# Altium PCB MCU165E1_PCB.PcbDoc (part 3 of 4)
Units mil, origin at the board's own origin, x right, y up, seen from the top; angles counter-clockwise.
Board outline 2658.83 x 2179.35 mil, 6 copper layers (Top Signal Layer, GND1, Mid Layer, PWR, GND2, Bottom Signal Layer), stack 60.4 mil thick; 226 components, 197 nets, 947 pads, 562 vias.
Unrouted connection lines stored in the file: 81.
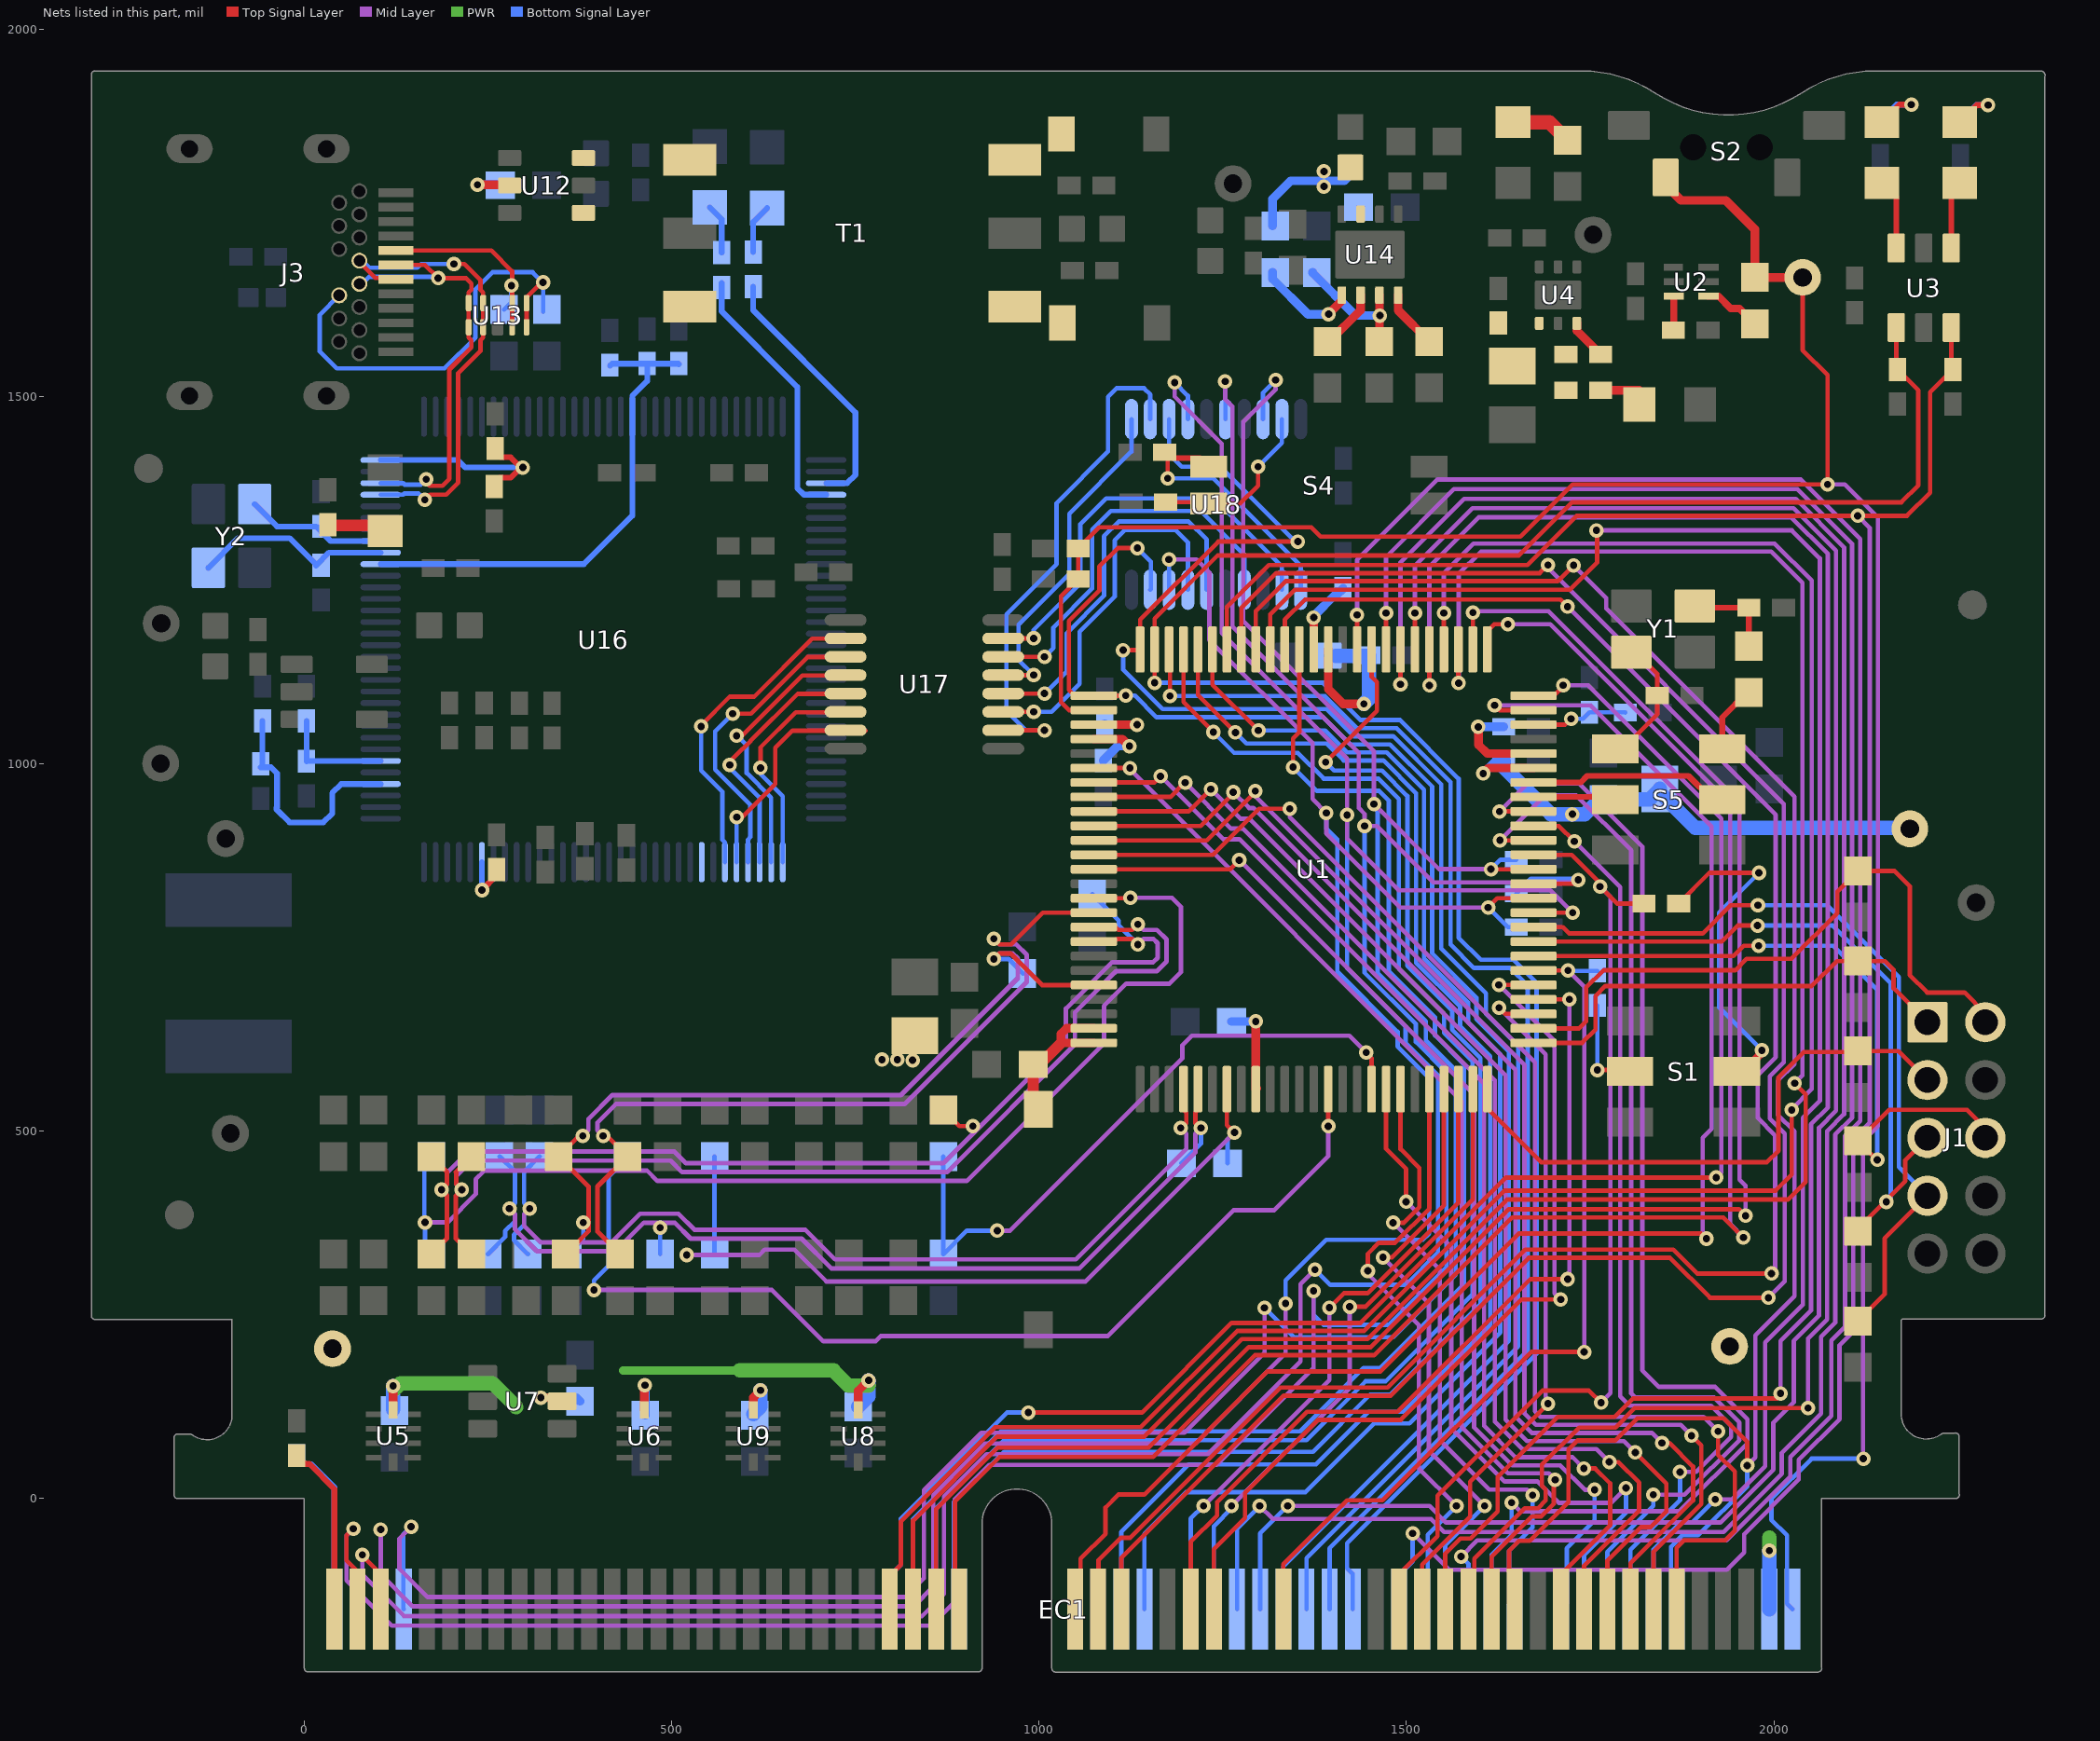
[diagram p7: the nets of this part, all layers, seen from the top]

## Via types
v1: diameter 19.68, hole 9.84, Top Signal Layer to Bottom Signal Layer, tented both sides, 540 vias
v2: diameter 23.62, hole 11.81, Top Signal Layer to Bottom Signal Layer, tented both sides, 16 vias
v3: diameter 19.68, hole 7.99, Top Signal Layer to Bottom Signal Layer, tented bottom, 4 vias
v4: diameter 19.68, hole 7.87, Top Signal Layer to Bottom Signal Layer, tented bottom, 2 vias

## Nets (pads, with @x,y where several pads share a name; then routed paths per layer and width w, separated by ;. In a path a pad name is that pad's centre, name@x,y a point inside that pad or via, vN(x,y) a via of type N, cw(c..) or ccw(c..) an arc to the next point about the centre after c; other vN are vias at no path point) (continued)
MCU_B2/C6/E12: C45.1 R42.1 U1.15 | length 1571.2
  Top Signal Layer w6: U1.15@1074.57,816.94 1123.72,816.94 v1(1124.28,817.5)
  Mid Layer w6: v1(164.39,375.65) 195.05,375.65 233.47,414.07 233.47,434.36 245.31,446.2 466.7,446.2 480.72,432.18 901.66,432.18 1088.46,618.98 1088.46,670.39 1118.73,700.66 1177.52,700.66 1193,716.14 1193,805.56 1181.06,817.5 v1(1124.28,817.5)
  Bottom Signal Layer w6: C45.1@157.33,460.85 163.33,454.86 163.33,376.71 v1(164.39,375.65) 164.39,341.21 R42.1@173.1,332.5
MCU_B4/C8: C47.1 R40.1 U1.39 | length 1433.5
  Top Signal Layer w6: U1.39@1393.47,557.1 1393.47,506.6 v1(1393.59,506.48)
  Mid Layer w6: v1(394.17,283.73) 636.45,283.73 706.21,213.97 777.55,213.97 784.71,221.13 1093.59,221.13 1264.68,392.22 1319.92,392.22 1393.59,465.89 v1(1393.59,506.48)
  Bottom Signal Layer w6: v1(394.17,283.73) 394.17,296.79 R40.1@429.89,332.5 414.17,348.22 414.17,437.83 429.95,453.61 C47.1@429.95,465.5
MCU_B5/D15/E15/PGA3_OUT: C43.1 C98.2 R44.1 U1.32 | length 1132.9
  Top Signal Layer w6: U1.32@1255.68,557.1 1255.68,508.32 v1(1265.91,498.09)
  Mid Layer w6: v1(520.47,331.39) 619.21,331.39 626.38,338.56 667.23,338.56 710.46,295.33 1063.15,295.33 v1(1265.91,498.09)
  Bottom Signal Layer w6: v1(520.47,331.39) 559.46,331.39 R44.1@558.35,332.5 C43.1@558.35,465.44 ; C98.2@1256.49,456.13 1256.49,488.67 v1(1265.91,498.09)
MCU_C14: C52.1 R49.1 U1.42 | length 904.2
  Top Signal Layer w6: v1(1445.09,606.85) 1452.53,599.41 U1.42@1452.53,557.1
  Mid Layer w6: v1(943.13,364.5) 960.66,364.5 1194.96,598.8 1194.96,616.76 1207.86,629.66 1422.28,629.66 v1(1445.09,606.85)
  Bottom Signal Layer w6: C52.1@869.74,465.44 R49.1@869.74,332.5 901.74,364.5 v1(943.13,364.5)
MCU_GPIO0: EC1.49 U1.79 | length 2999.7
  Top Signal Layer w6: EC1.49@796.97,-150.67 796.97,-104.87 811.95,-89.89 811.95,-31.19 940.07,96.93 1138.44,96.93 1269.43,227.92 1442.28,227.92 1633.3,418.94 2002.41,418.94 2024.18,440.71 v1(2024.18,528.79) ; U1.79@1550.95,1155.53 v1@1550.95,1204.96
  Mid Layer w6: v1(1550.93,1204.98) 1550.93,1259.6 1591.02,1299.69 2001.03,1299.69 2051.56,1249.16 2051.56,557.22 2024.18,529.84 v1(2024.18,528.79)
  PWR w6: v1(2024.18,528.79) 2024.18,530.06 v1@2026.3,532.18
MCU_GPIO1: EC1.51 U1.78 | length 3044.7
  Top Signal Layer w6: EC1.51@828.46,-150.67 828.46,-30.23 942.88,84.18 1143.1,84.18 1275.84,216.92 1446.84,216.92 1636.72,406.8 2019.08,406.8 2043.21,430.93 2043.21,550.15 v1(2028.37,564.99) ; U1.78@1570.64,1155.53 1570.64,1110.09 v1(1571.09,1109.64)
  Mid Layer w6: v1(1571.09,1109.64) 1571.09,1258.09 1601.69,1288.69 1996.48,1288.69 2039,1246.16 2039,575.62 v1(2028.37,564.99)
MCU_GPIO2: EC1.53 U1.77 | length 2498.3
  Top Signal Layer w6: EC1.53@859.96,-150.67 859.96,-14.29 943.47,69.22 1148.9,69.22 1285.6,205.92 1451.39,205.92 1639.03,393.56 1952.55,393.56 v1(1961.39,384.72) ; U1.77@1590.32,1155.53 1590.32,1205.57 v1(1590.44,1205.69)
  Mid Layer w6: v1(1590.44,1205.69) 1592.34,1207.59 1693.5,1207.59 1953.32,947.78 1953.32,433.84 1961.39,425.77 v1(1961.39,384.72)
MCU_GPIO3: EC1.55 U1.76 | length 2442.8
  Top Signal Layer w6: EC1.55@885.42,-144.63 885.42,-4.39 946.4,56.59 1155.51,56.59 1293.84,194.92 1455.95,194.92 1643.59,382.56 1931.3,382.56 v1(1958.56,355.3) ; U1.76@1610.01,1155.53 1610.01,1180.41 1619.35,1189.75 v1(1637.92,1189.75)
  Mid Layer w6: v1(1637.92,1189.75) 1695.79,1189.75 1940.57,944.97 1940.57,373.29 v1(1958.56,355.3)
MCU_GPIO4: EC1.50 U1.75 | length 2260.9
  Top Signal Layer w6: v1(985.4,116.92) 1139.94,116.92 1261.94,238.92 1437.72,238.92 1635.59,436.79 v1(1921.48,436.79) ; U1.75@1673,1092.54 1700.77,1092.54 1713.28,1105.05 v1(1713.28,1106.65)
  Mid Layer w6: v1(1713.28,1106.65) 1747.37,1106.65 1928.6,925.42 1928.6,443.36 1921.99,436.75 v1(1921.48,436.79) v1(1921.48,436.79)
  PWR w6: v1@1921.48,436.58 v1(1921.48,436.79)
  Bottom Signal Layer w6: EC1.50@796.97,-150.67 796.97,-104.87 811.95,-89.89 811.95,-27.38 956.25,116.92 v1(985.4,116.92)
MCU_GPIO5: EC1.52 U1.89 | length 2018.6
  Top Signal Layer w6: v1(1345.51,995.35) 1345.51,1034.23 1354.1,1042.82 U1.89@1354.1,1155.53
  Bottom Signal Layer w6: EC1.52@828.46,-150.67 828.46,-27.92 947.74,91.36 1355.01,91.36 1441.36,177.71 1464.15,177.71 1578.27,291.83 1578.27,590.77 1538.87,630.17 1538.87,654.77 1475.92,717.72 1475.92,950.23 1463.15,963 1377.86,963 v1(1345.51,995.35)
MCU_GPIO6: EC1.54 U1.97 | length 2123
  Top Signal Layer w6: U1.97@1196.62,1155.53 1196.62,1084.06 1237.14,1043.54 v1(1237.14,1043.02)
  Bottom Signal Layer w6: EC1.54@859.96,-150.67 859.96,-13.3 952.38,79.12 1363.97,79.12 1444.37,159.52 1471.64,159.52 1589.72,277.6 1589.72,594.88 1551.11,633.49 1551.11,659.73 1489.56,721.28 1489.56,952.15 1462,979.71 1387.3,979.71 1352.27,1014.74 1265.42,1014.74 v1(1237.14,1043.02)
MCU_GPIO7: EC1.56 U1.84 | length 2015.3
  Top Signal Layer w6: v1(1390.01,1002.23) 1459.76,1071.98 1459.76,1111.09 1452.53,1118.32 U1.84@1452.53,1155.53
  Bottom Signal Layer w6: EC1.56@884.28,-143.49 884.28,-4.54 952.29,63.47 1372.94,63.47 1450.6,141.13 1477.64,141.13 1600.78,264.27 1600.78,599.37 1562.11,638.04 1562.11,664.29 1501.22,725.18 1501.22,956.05 1466.56,990.71 1401.53,990.71 v1(1390.01,1002.23)
MCU_GPIO8: EC1.57 U1.74 | length 2107.5
  Top Signal Layer w6: EC1.57@1056.53,-143.08 1056.53,-82.1 1090.44,-48.19 1090.44,-12.37 1108.09,5.29 1143.24,5.29 1310.87,172.92 1465.06,172.92 1652.7,360.56 1901.29,360.56 v1(1908.25,353.6) ; v1(1619.96,1079.41) 1626.52,1072.85 U1.74@1673,1072.85
  Mid Layer w6: v1(1619.96,1079.41) 1750.52,1079.41 1915.27,914.66 1915.27,502.95 1903.1,490.78 1903.1,358.75 v1(1908.25,353.6)
MCU_GPIO9: EC1.59 U1.90 | length 2659.5
  Top Signal Layer w6: EC1.59@1080.72,-151.11 1080.72,-84.17 1111.33,-53.57 1124.07,-53.57 1328.56,150.92 1474.18,150.92 1661.82,338.56 1863.21,338.56 1895.73,306.04 v1(1996.84,306.04) ; U1.90@1334.42,1155.53 1334.42,1196.03 1361.92,1223.53 1709.51,1223.53 v1(1719.3,1213.74)
  Mid Layer w6: v1(1719.3,1213.74) 2002.51,930.53 2002.51,600.73 1977.95,576.17 1977.95,517.94 2001.76,494.13 2001.76,310.96 v1(1996.84,306.04)
MCU_GPIO10: EC1.61 U1.93 | length 2795.2
  Top Signal Layer w6: EC1.61@1111.93,-150.67 1111.93,-81.27 1333.12,139.92 1478.73,139.92 1666.37,327.56 1858.65,327.56 1913.06,273.15 v1(1992.58,273.15) ; U1.93@1275.36,1155.53 1275.36,1212.04 1322.73,1259.41 1681.4,1259.41 1692.31,1270.32 v1(1692.45,1270.32)
  Mid Layer w6: v1(1692.45,1270.32) 1692.45,1266.29 2013.51,945.23 2013.51,593.41 1994.56,574.46 1994.56,516.88 2014.68,496.76 2014.68,295.25 v1(1992.58,273.15)
MCU_GPIO11: J1.2 R4.2 U1.52 | length 910.8
  Top Signal Layer w6: U1.52@1673,639.78 1735.12,639.78 1744.58,649.24 1744.58,695.46 1767.92,718.8 1947.46,718.8 1962.99,734.33 2023.96,734.33 2086.47,796.84 2086.47,826.05 R4.2@2114.35,853.93 2164.37,853.93 2185.03,833.27 2185.03,712.19 2208.66,688.56 2259.44,688.56 2287.74,660.26 J1.2@2287.74,648.22
MCU_GPIO12: J1.1 R3.2 U1.51 | length 658.1
  Top Signal Layer w6: U1.51@1673,620.09 1739.11,620.09 1757.19,638.17 1757.19,683.87 1770.73,697.41 2051.67,697.41 2085.71,731.45 R3.2@2114.35,731.45 2150.91,731.45 2162.95,719.41 2162.95,694.27 J1.1@2209,648.22
MCU_GPIO13: J1.3 R5.2 U1.50 | length 774.3
  Top Signal Layer w6: U1.50@1610.01,557.1 1610.01,531.05 1683.33,457.73 1990.71,457.73 2006.25,473.27 2006.25,573.15 2040.56,607.46 R5.2@2096.34,607.46 ; R5.2@2114.35,608.97 2169.51,608.97 J1.3@2209,569.48
MCU_GPIO14: EC1.62 U1.96 | length 1903.3
  Top Signal Layer w6: U1.96@1216.31,1155.53 1216.31,1093.43 v1(1267.26,1042.48)
  Bottom Signal Layer w6: EC1.62@1111.93,-150.67 1111.93,-45.59 1203.83,46.31 1376.92,46.31 1448.61,118 1495.79,118 1613.83,236.04 1613.83,601.88 1573.11,642.6 1573.11,668.84 1512.98,728.97 1512.98,959.84 1468.45,1004.37 1414.53,1004.37 1391.57,1027.33 1282.41,1027.33 v1(1267.26,1042.48)
MCU_GPIO15: EC1.64 U1.95 | length 1877
  Top Signal Layer w6: U1.95@1235.99,1155.53 1235.99,1107.64 v1(1298.46,1045.17)
  Bottom Signal Layer w6: EC1.64@1143.42,-150.67 1143.42,-48.12 1200.18,8.64 1362.72,8.64 1456.15,102.07 1504,102.07 1627.65,225.72 1627.65,604.62 1584.11,648.16 1584.11,675.08 1523.98,735.21 1523.98,964.4 1473.01,1015.37 1419.09,1015.37 1389.29,1045.17 v1(1298.46,1045.17)
MCU_GPIO16: EC1.67 U1.54 | length 1208.9
  Top Signal Layer w6: EC1.67@1206.42,-150.67 1206.42,-58.98 1242.22,-23.18 1242.22,-4.76 1364.91,117.92 1487.84,117.92 1668.34,298.42 v1(1719.43,298.42) ; U1.54@1673,679.15 v1(1721.88,679.15)
  Mid Layer w6: v1@1717.42,679.15 v1(1721.88,679.15) 1721.88,297.88 v1@1719.43,295.43 ; v1@1717.6,293.6 v1@1719.43,295.43 ; v1(1719.43,298.42) v1@1719.43,295.43
  PWR w6: v1@1718.2,297.19 v1(1719.43,298.42)
MCU_GPIO17: EC1.69 U1.55 | length 1224.4
  Top Signal Layer w6: EC1.69@1237.91,-150.67 1237.91,-69.16 1280.49,-26.58 1280.49,7.51 1379.9,106.92 1492.4,106.92 1656.34,270.86 v1(1709.98,270.86) ; v1(1625.8,698.83) U1.55@1673,698.83
  Mid Layer w6: v1(1625.8,698.83) 1701.58,623.05 1701.58,279.26 v1(1709.98,270.86)
MCU_GPIO18/X2: S5.2 U1.68 | length 112.6
  Top Signal Layer w8: U1.68@1673,954.74 1780.69,954.74 S5.2@1784.17,951.26
MCU_GPIO19/X1: S5.5 U1.69 | length 273.9
  Top Signal Layer w8: U1.69@1673,974.43 1737.06,974.43 1746.02,983.39 1883.82,983.39 1915.95,951.26 S5.5@1929.83,951.26
MCU_GPIO20: EC1.68 U1.48 | length 877.5
  Top Signal Layer w6: v1(1395.14,259.6) 1414.84,279.3 1446.99,279.3 1570.64,402.95 U1.48@1570.64,557.1
  Mid Layer w6: v1(1223.78,-10.2) 1395.14,161.16 v1(1395.14,259.6)
  Bottom Signal Layer w6: EC1.68@1206.42,-150.67 1206.42,-27.57 v1(1223.78,-10.2)
MCU_GPIO21: EC1.70 U1.49 | length 864.7
  Top Signal Layer w6: v1(1422.83,260.95) 1444.2,260.95 1590.32,407.07 U1.49@1590.32,557.1
  Mid Layer w6: v1(1262.02,-10.2) 1422.83,150.61 v1(1422.83,260.95)
  Bottom Signal Layer w6: EC1.70@1237.91,-150.67 1237.91,-37.75 v1@1263.38,-12.28
MCU_GPIO22: EC1.72 U1.83 | length 3045
  Top Signal Layer w6: v1@1299.1,-17.04 v1@1300.31,-17.04 ; U1.83@1472.21,1155.53 v1(1472.2,1205.03)
  Mid Layer w6: v1(1300.25,-10.2) 1318.09,-28.04 1533.68,-28.04 1551.2,-45.57 1931.56,-45.57 2010.78,33.66 2010.78,62.07 2064.37,115.66 2064.37,220.04 2083.51,239.17 2083.51,495.41 2106.56,518.46 2106.56,1299.16 2032.1,1373.62 1564.33,1373.62 1472.2,1281.49 v1(1472.2,1205.03)
  Bottom Signal Layer w6: EC1.72@1269.41,-150.67 1269.41,-41.27 1298.91,-11.77 v1@1299.1,-11.77
MCU_GPIO23: EC1.74 U1.81 | length 2885.6
  Top Signal Layer w6: U1.81@1511.58,1155.53 v1(1511.57,1205.11)
  Mid Layer w6: v1(1338.49,-10.2) 1531.39,-10.2 1553.88,-32.69 1927.17,-32.69 1999.32,39.46 1999.32,103.18 2027.06,130.92 2027.06,214.54 2061.51,248.99 2061.51,504.52 2084.56,527.57 2084.56,1290.05 2026.79,1347.82 1589.84,1347.82 1511.57,1269.55 v1(1511.57,1205.11)
  Bottom Signal Layer w6: EC1.74@1300.9,-150.67 1300.9,-47.47 1337.71,-10.66 v1@1338.79,-10.66
MCU_GPIO24: EC1.75 R9.2 U1.56 | length 1215.7
  Top Signal Layer w6: EC1.75@1332.4,-150.67 1332.4,-89.56 1419.26,-2.7 1467.55,-2.7 1669.67,199.42 v1(1741.85,199.42) ; U1.56@1673,718.52 v1(1719.72,718.52)
  Mid Layer w6: v1(1719.72,718.52) 1741.96,696.28 1741.96,194.35 1741.85,194.46 v1(1741.85,199.42)
  Bottom Signal Layer w6: v1(1719.72,718.52) 1720.17,718.07 R9.2@1759.8,718.07
MCU_GPIO25: J1.6 R6.2 U1.57 | length 981.7
  Top Signal Layer w6: U1.57@1673,738.2 1944.93,738.2 1958.95,752.22 v1(1979.36,752.22) ; v1(2140.82,460.85) 2139.99,460.85 R6.2@2114.35,486.49 2156.86,529 2263,529 2287.74,504.26 J1.6@2287.74,490.74
  Bottom Signal Layer w6: v1(1979.36,752.22) 2080.8,752.22 2140.82,692.2 v1(2140.82,460.85)
MCU_GPIO26: J1.5 R7.2 U1.58 | length 993.5
  Top Signal Layer w6: U1.58@1673,757.89 1673.11,758 1928.91,758 1950.69,779.78 v1(1977.82,779.78) ; R7.2@2114.35,364.02 2114.35,367.36 2178.78,431.79 2178.78,460.52 J1.5@2209,490.74
  Bottom Signal Layer w6: v1(1977.82,779.78) 2080.13,779.78 2159.18,700.73 2159.18,409.89 v1(2152.98,403.69)
MCU_GPIO27: J1.7 R8.2 U1.59 | length 1080.6
  Top Signal Layer w6: U1.59@1673,777.57 1712.99,777.57 1721.56,769 1903.05,769 1941.43,807.38 v1(1978.3,807.38) ; R8.2@2114.35,241.54 2150.74,277.93 2150.74,353.74 J1.7@2209,412
  Bottom Signal Layer w6: v1(1978.3,807.38) 2072.55,807.38 2170.18,709.75 2170.18,450.82 J1.7@2209,412
MCU_GPIO28: EC1.76 U1.1 U18.9 | length 2150.5
  Top Signal Layer w6: v1(1117.96,1092.69) 1117.81,1092.54 U1.1@1074.57,1092.54 1048.54,1092.54 1040.65,1100.43 1040.65,1193.98 1082.11,1235.44 1082.11,1268.24 1107.27,1293.4 v1(1133.82,1293.4)
  Bottom Signal Layer w6: v1(1117.96,1092.69) 1130.63,1092.69 1160.05,1063.27 1386.75,1063.27 1423.64,1026.37 1477.56,1026.37 1534.98,968.95 1534.98,742.06 1595.11,681.93 1595.11,652.72 1639.3,608.53 1639.3,214.24 1332.4,-92.66 EC1.76@1332.4,-150.67 ; v1(1133.82,1293.4) 1152.08,1275.14 1152.08,1237.51 U18.9@1151.34,1236.77
MCU_GPIO29: EC1.78 U1.100 U18.13 | length 2404.6
  Top Signal Layer w6: v1(1114.35,1154.57) 1136.61,1154.57 U1.100@1137.57,1155.53 1137.57,1196.03 1243.91,1302.37 v1(1352.21,1302.37)
  Bottom Signal Layer w6: v1(1114.35,1154.57) 1114.35,1128.05 1168.13,1074.27 1391.3,1074.27 1428.2,1037.37 1482.12,1037.37 1547.51,971.98 1547.51,748.15 1608.25,687.41 1608.25,659.87 1652.16,615.96 1652.16,207.01 1363.9,-81.25 EC1.78@1363.9,-150.67 ; U18.13@1176.93,1469.06 1176.93,1421.65 1194.38,1404.2 1246.93,1404.2 1348.76,1302.37 v1(1352.21,1302.37)
MCU_GPIO30: EC1.80 U1.98 | length 1804.1
  Top Signal Layer w6: U1.98@1176.94,1155.53 1178.21,1154.25 1178.21,1092.11 v1(1178.26,1092.11)
  Bottom Signal Layer w6: v1(1178.26,1092.11) 1389.02,1092.11 1432.76,1048.37 1486.68,1048.37 1559.92,975.13 1559.92,753.85 1591.71,722.06 1641.29,722.06 1664.99,698.36 1664.99,201.5 1395.39,-68.09 EC1.80@1395.39,-150.67
MCU_GPIO31: EC1.82 R21.1 U1.99 U3.1 | length 3204.7
  Top Signal Layer w6: v1(1157.4,1110.23) 1157.4,1155.38 U1.99@1157.25,1155.53 1157.25,1197.55 1243.22,1283.52 1653.12,1283.52 1725.39,1355.79 2173.57,1355.79 2196.58,1378.8 2196.58,1508.23 R21.1@2168.19,1536.62 ; R21.1@2166.6,1538.21 U3.1@2166.6,1593.58
  Bottom Signal Layer w6: v1(1157.4,1110.23) 1386.45,1110.23 1437.31,1059.37 1491.23,1059.37 1571.12,979.48 1571.12,763.19 1601.25,733.06 1645.85,733.06 1676.99,701.92 1676.99,196.66 1419.21,-61.12 1419.21,-94.83 1426.89,-102.51 EC1.82@1426.89,-150.67
MCU_GPIO32: EC1.85 R10.1 U1.64 | length 1358.9
  Top Signal Layer w6: EC1.85@1489.88,-150.67 1489.88,-103.5 1542.24,-51.14 1542.24,3.83 1685.23,146.82 1748.42,146.82 v1(1764.83,130.41) ; U1.64@1673,876 1724.84,876 1763.37,837.47 v1(1763.37,832.9) 1786.62,809.65 R10.1@1823.26,809.65
  Mid Layer w6: v1(1763.37,832.9) 1777.64,818.63 1777.64,143.22 v1(1764.83,130.41)
MCU_GPIO33: EC1.87 U1.53 | length 967.3
  Top Signal Layer w6: EC1.87@1521.38,-150.67 1521.38,-89.9 1586.62,-24.66 1586.62,22.98 v1(1692.62,128.98) ; v1(1626.09,667.8) 1634.43,659.46 U1.53@1673,659.46
  Mid Layer w6: v1(1626.09,667.8) 1689.54,604.35 1689.54,132.06 v1(1692.62,128.98)
MCU_GPIO34: EC1.86 R22.1 U1.94 U3.3 | length 3395.3
  Top Signal Layer w6: U1.94@1255.68,1155.53 1255.68,1213.54 1312.55,1270.41 1664.59,1270.41 1731.39,1337.21 v1@2114.07,1337.21 ; v1(2114.07,1337.32) 2181.15,1337.32 2212.53,1368.7 2212.53,1505.55 R22.1@2243.61,1536.62 ; R22.1@2241.4,1538.83 U3.3@2241.4,1593.58
  Mid Layer w6: v1(1508.47,-47.45) 1557.95,-96.93 1936.22,-96.93 1959.62,-73.53 1959.62,-48.62 2033.97,25.73 2033.97,52.39 2089.35,107.77 2089.35,208.57 2107.9,227.12 2107.9,488.69 2130.48,511.27 2130.48,1320.91 v1(2114.07,1337.32)
  Bottom Signal Layer w6: EC1.86@1489.91,-150.64 1489.91,-104.09 1508.47,-85.53 v1(1508.47,-47.45)
MCU_GPIO35/TDI: EC1.8 R11.1 U1.63 U18.18 | length 3664.7
  Top Signal Layer w6: v1(1614.98,856.43) 1615.1,856.32 U1.63@1673,856.32
  Mid Layer w6: v1(145.49,-38.49) 129.5,-54.48 129.5,-95.6 168.13,-134.23 817.99,-134.23 843.48,-108.74 843.48,11.3 921.51,89.33 1197.88,89.33 1306.81,198.26 v1(1306.81,259.36) ; v1(1321.92,1522.17) 1321.92,1509.3 1277.9,1465.28 1277.9,1194.44 1455.76,1016.58 v1(1455.76,945.16) 1544.49,856.43 v1(1614.98,856.43)
  Bottom Signal Layer w6: EC1.8@135.55,-150.67 134.93,-150.05 134.93,-49.05 v1(145.49,-38.49) ; U18.18@1304.88,1469.06 1304.88,1505.13 v1(1321.92,1522.17) ; v1(1306.81,259.36) 1346.81,219.36 1481.9,219.36 1567.01,304.47 1567.01,582.73 1526.26,623.48 1526.26,649.4 1460.85,714.81 1460.85,940.07 v1(1455.76,945.16) ; v1(1614.98,856.43) 1627.92,869.37 R11.1@1649.38,869.37
MCU_GPIO37/TDO: EC1.6 R12.1 U1.61 U18.8 | length 3488.7
  Top Signal Layer w6: v1(1611.11,804.37) 1623.68,816.94 U1.61@1673,816.94
  Mid Layer w6: v1(103.99,-42.19) 103.99,-102.98 147.88,-146.87 829.36,-146.87 856.08,-120.15 856.08,4.38 926.63,74.93 1212.79,74.93 1335.53,197.67 v1(1335.53,265.38) ; v1(1176.71,1277.87) 1214.17,1277.87 1231.68,1260.36 1231.68,1168.51 1372.17,1028.02 1372.17,951.87 v1@1390.95,933.09 ; v1(1390.89,933.03) 1390.89,905.27 1491.79,804.37 v1(1611.11,804.37)
  Bottom Signal Layer w6: v1(103.99,-42.19) 103.99,-150.61 EC1.6@104.05,-150.67 ; v1(1176.71,1277.87) 1176.93,1277.65 U18.8@1176.93,1236.77 ; v1(1335.53,265.38) 1335.53,296.75 1390.66,351.88 1522.21,351.88 1530.7,360.37 1530.7,572.37 1487.96,615.11 1487.96,635.18 1405.74,717.39 1405.74,897.1 1390.89,911.95 v1(1390.89,933.03) ; v1(1611.11,804.37) 1637.91,777.57 R12.1@1649.38,777.57
MCU_GPIO40: EC1.89 U1.80 | length 2622.8
  Top Signal Layer w6: v1(1531.25,1106.56) U1.80@1531.27,1155.53 ; EC1.89@1552.87,-150.67 1552.87,-74.81 1573.3,-54.39 1587.36,-54.39 1624.16,-17.59 1624.16,29.01 1706.01,110.86 1783.11,110.86 1808.17,135.92 2004.8,135.92 v1@2011.63,142.75
  Mid Layer w6: v1(1531.25,1106.56) 1531.25,1268.41 1598.21,1335.37 2023.68,1335.37 2073.56,1285.49 2073.56,532.13 2050.51,509.08 2050.51,255.57 2009.22,214.28 v1(2009.22,142.94)
MCU_GPIO41: EC1.91 U1.82 | length 2719.3
  Top Signal Layer w6: v1(1491.84,1107.91) 1491.9,1107.97 U1.82@1491.9,1155.53 ; EC1.91@1584.37,-150.67 1592.22,-142.82 1592.22,-81.85 1660.78,-13.29 1679.02,-13.29 1689.47,-2.84 1689.47,11.94 1684.44,16.98 1684.44,46.04 1734.94,96.55 1784.36,96.55 1810.86,123.05 v1(2046.53,123.05)
  Mid Layer w6: v1(1491.84,1107.91) 1491.84,1273.8 1578.45,1360.41 2029.75,1360.41 2095.56,1294.6 2095.56,523.02 2072.51,499.97 2072.51,243.73 2046.53,217.75 v1(2046.53,123.05)
MCU_GPIO44: EC1.92 U1.85 | length 2770.1
  Top Signal Layer w6: v1(1432.73,1202.65) 1432.84,1202.54 U1.85@1432.84,1155.53
  Mid Layer w6: v1(1432.73,1202.65) 1432.73,1277.44 1542.18,1386.89 2036.6,1386.89 2117.56,1305.93 2117.56,513.9 2096.9,493.24 2096.9,233.49 2078.35,214.94 2078.35,112.33 2022.25,56.23 2022.25,29.57 1935.6,-57.08 1596.39,-57.08 v1(1574.38,-79.09)
  Bottom Signal Layer w6: v1(1574.38,-79.09) 1584.37,-89.08 EC1.92@1584.37,-150.67
MCU_GPIO47: EC1.93 U1.6 | length 1509.1
  Top Signal Layer w6: U1.6@1074.57,994.11 v1(1123.64,994.08) ; EC1.93@1615.87,-150.67 1615.87,-79.46 1671.03,-24.29 1683.58,-24.29 1700.47,-7.4 1700.47,23.69 v1(1702.28,25.5)
  Mid Layer w6: v1(1123.64,994.08) 1123.64,992.29 1575.24,540.69 1575.24,97.19 1638.29,34.14 1693.64,34.14 v1(1702.28,25.5)
MCU_GPIO48: EC1.99 U1.7 | length 1576.3
  Top Signal Layer w6: U1.7@1074.57,974.43 1156.9,974.43 v1(1165.26,982.79) ; EC1.99@1710.35,-150.67 1710.35,-103.43 1777.23,-36.55 1777.23,20.62 1756.95,40.9 v1(1741.27,40.9)
  Mid Layer w6: v1(1165.26,982.79) 1250.81,897.24 1272.58,897.24 1605.61,564.21 1605.61,98.7 1648.17,56.14 1726.03,56.14 v1(1741.27,40.9)
MCU_GPIO49: EC1.101 U1.8 | length 1620.2
  Top Signal Layer w6: U1.8@1074.57,954.74 1178.59,954.74 1198.18,974.33 v1(1198.97,974.33) ; EC1.101@1741.85,-150.67 1741.85,-91.3 1816.6,-16.55 1816.6,21.58 1788.55,49.63 v1(1776.06,49.63)
  Mid Layer w6: v1(1198.97,974.33) 1261.59,911.71 1277.76,911.71 1620.31,569.16 1620.31,104.46 1657.63,67.14 1758.55,67.14 v1(1776.06,49.63)
MCU_GPIO50: EC1.103 U1.9 | length 1669.8
  Top Signal Layer w6: U1.9@1074.57,935.06 1203.44,935.06 v1(1233.79,965.41) ; EC1.103@1773.35,-150.67 1773.35,-84.77 1819.09,-39.03 1832.35,-39.03 1853.79,-17.59 1853.79,20.22 v1(1811.37,62.64)
  Mid Layer w6: v1(1233.79,965.41) 1274.03,925.17 1285.85,925.17 1635.01,576.01 1635.01,107.44 1664.31,78.14 1795.87,78.14 v1(1811.37,62.64)
MCU_GPIO51: EC1.105 U1.10 | length 1721.3
  Top Signal Layer w6: U1.10@1074.57,915.37 1220.05,915.37 1264.21,959.53 v1(1264.21,961.19) ; EC1.105@1804.84,-150.67 1804.84,-88.15 1890.14,-2.85 1890.14,43.38 1857.96,75.56 v1(1847.69,75.56)
  Mid Layer w6: v1(1264.21,961.19) 1285.75,939.65 1291.74,939.65 1648.05,583.34 1648.05,111.74 1670.65,89.14 1834.11,89.14 v1(1847.69,75.56)
MCU_GPIO52: EC1.107 U1.11 | length 1755.1
  Top Signal Layer w6: U1.11@1074.57,895.69 1228.34,895.69 1294.31,961.66 v1(1294.31,962.66) ; EC1.107@1836.34,-150.67 1836.34,-72.21 1901.14,-7.41 1901.14,72.27 v1(1888.05,85.36)
  Mid Layer w6: v1(1294.31,962.66) 1294.31,956.05 1660.67,589.69 1660.67,115.64 1676.17,100.14 1873.27,100.14 v1(1888.05,85.36)
MCU_GPIO53: EC1.109 U1.12 | length 1836
  Top Signal Layer w6: U1.12@1074.57,876 1236.68,876 1299.48,938.8 v1(1341.15,938.8) ; EC1.109@1860.63,-150.67 EC1.109@1867.83,-150.67 1867.55,-150.38 1867.55,-67.53 1878,-57.08 1933.82,-57.08 1946.83,-44.07 1946.83,36.5 1924.13,59.21 v1(1924.13,91.39)
  Mid Layer w6: v1(1341.15,938.8) 1341.15,927.18 1674.78,593.55 1674.78,118.53 1682.17,111.14 1904.38,111.14 v1(1924.13,91.39)
MCU_GPIO54: EC1.100 U1.13 | length 1495
  Top Signal Layer w6: U1.13@1074.57,856.32 1259.98,856.32 v1(1272.41,868.75) v1@1277.47,873.81
  Mid Layer w6: v1(1272.41,868.75) 1592.16,549 1592.16,96.59 1643.62,45.14 1709.38,45.14 1742.75,11.77 v1(1755.93,11.77)
  Bottom Signal Layer w6: EC1.100@1710.35,-150.67 1718.23,-142.79 1718.23,-67.81 1755.93,-30.11 v1(1755.93,11.77)
MCU_GPIO55: EC1.102 U1.43 | length 974.8
  Top Signal Layer w6: U1.43@1472.21,557.1 1472.21,475.92 1499.56,448.57 v1(1499.56,403.77)
  Mid Layer w6: v1(1499.56,403.77) 1560.92,342.41 1560.92,95.95 1633.75,23.12 1678.43,23.12 1707.62,-6.07 1778.5,-6.07 v1(1798.76,14.19)
  Bottom Signal Layer w6: EC1.102@1741.85,-150.67 1741.85,-76.7 1798.76,-19.79 v1(1798.76,14.19)
MCU_GPIO56: EC1.104 U1.65 | length 1536.7
  Top Signal Layer w6: v1(1627.21,895.78) 1627.3,895.69 U1.65@1673,895.69
  Mid Layer w6: v1(1627.21,895.78) 1688.17,956.74 1731.22,956.74 1805.92,882.04 1805.92,142.8 1810.96,137.76 1918.55,137.76 1952.97,103.34 1952.97,79.44 1878.46,4.93 v1(1835.95,4.93)
  Bottom Signal Layer w6: EC1.104@1773.35,-150.67 1773.35,-72.81 1835.95,-10.2 v1(1835.95,4.93)
MCU_GPIO57: EC1.106 U1.66 | length 1332.1
  Top Signal Layer w6: U1.66@1673,915.37 1707.46,915.37 v1(1728.55,894.28)
  Mid Layer w6: v1(1728.55,894.28) 1790.79,832.04 1790.79,139.09 1803.68,126.2 1914.55,126.2 1941.97,98.78 1941.97,84 1893.96,35.99 v1(1872.3,35.99)
  Bottom Signal Layer w6: EC1.106@1804.84,-150.67 1804.84,-69.71 1872.3,-2.25 v1(1872.3,35.99)
MCU_GPIO58: EC1.94 U1.67 | length 1728.2
  Top Signal Layer w6: v1(1626.72,934.96) 1626.82,935.06 U1.67@1673,935.06
  Mid Layer w6: v1(1626.72,934.96) 1664.75,972.99 1735.2,972.99 1820.96,887.23 1820.96,174.65 1843.83,151.78 1920.09,151.78 1963.97,107.89 1963.97,74.89 1871.68,-17.41 1654.81,-17.41 v1(1643.12,-5.72)
  Bottom Signal Layer w6: EC1.94@1615.87,-150.67 1615.87,-76.56 1643.12,-49.31 v1(1643.12,-5.72)
MCU_GPIO59: EC1.95 EC1.110 U1.92 | length 2729.3
  Top Signal Layer w6: U1.92@1294.73,1155.84 U1.92@1295.05,1155.53 1295.05,1207.87 1335.59,1248.41 1705.83,1248.41 v1(1727.43,1270.01) ; EC1.95@1647.36,-150.67 1639.66,-142.97 1639.66,-71.22 1653.04,-57.84 1667.8,-57.84 1720.5,-5.14 1720.5,66.55 1732.83,78.88 1783.72,78.88 1814.07,109.23 1931.52,109.23 1963.82,76.93 v1(1963.82,44.75)
  Mid Layer w6: v1(1727.43,1270.01) 1771.77,1225.67 1771.77,1211.17 2028,954.94 2028,591.41 2005.56,568.97 2005.56,522.09 2028,499.65 2028,275.14 1974.97,222.11 1974.97,55.9 v1(1963.82,44.75)
  Bottom Signal Layer w6: EC1.110@1867.83,-150.67 1867.83,-103.96 1859.96,-96.09 1859.96,-65.71 1875.43,-50.24 1896.96,-50.24 1963.82,16.62 v1(1963.82,44.75)
MCU_GPIO60: EC1.96 U1.44 | length 866.8
  Top Signal Layer w6: v1(1481.75,375.28) 1496.3,375.28 1517.4,396.38 1517.4,449.91 1491.9,475.41 U1.44@1491.9,557.1
  Mid Layer w6: v1(1481.75,375.28) 1545.47,311.56 1545.47,79.39 1612.74,12.12 1664.06,12.12 v1(1671.63,4.55)
  Bottom Signal Layer w6: EC1.96@1647.36,-150.67 1647.36,-104.91 1639.61,-97.16 1639.61,-71.65 1671.63,-39.63 v1(1671.63,4.55)
MCU_GPIO61: EC1.108 U1.91 | length 2436.3
  Top Signal Layer w6: U1.91@1314.73,1155.53 1314.73,1203.39 1348.22,1236.88 1722.53,1236.88 1759.64,1273.99 v1@1759.64,1322.01
  Mid Layer w6: v1(1758.55,1317.53) 2024.54,1317.53 2062.56,1279.51 2062.56,541.15 2039.51,518.1 2039.51,263.55 1988.25,212.29 1988.25,43.95 1942.92,-1.38 v1(1920.33,-1.38)
  Bottom Signal Layer w6: EC1.108@1836.34,-150.67 1836.34,-69.31 1873.4,-32.25 1889.46,-32.25 v1(1920.33,-1.38)
MCU_GPIO62: EC1.88 U1.46 | length 824.7
  Top Signal Layer w6: v1(1447.45,309.69) 1447.45,332.9 1462.45,347.9 1484.48,347.9 1531.27,394.69 U1.46@1531.27,557.1
  Mid Layer w6: v1(1447.45,309.69) 1447.45,305.43 1517.06,235.82 1517.06,40.83 v1(1568.09,-10.2)
  Bottom Signal Layer w6: EC1.88@1521.38,-150.67 1528.86,-143.19 1528.86,-49.43 v1(1568.09,-10.2)
MCU_GPIO63: EC1.90 U1.47 | length 828.8
  Top Signal Layer w6: v1(1467.95,328.17) 1480.3,328.17 1550.95,398.82 U1.47@1550.95,557.1
  Mid Layer w6: v1(1467.95,328.17) 1530.52,265.6 1530.52,65.6 v1(1606.32,-10.2)
  Bottom Signal Layer w6: EC1.90@1552.87,-150.67 1552.87,-63.65 v1(1606.32,-10.2)
MCU_PGA1_IN_N: C32.1 C96.1 R29.1 R94.1 U1.18 | length 1586.8
  Top Signal Layer w6.2: R94.1@172.97,332.5 194.17,353.7 194.17,412.83 v1(186.8,420.19) 194.17,427.55 ; C32.1@173.03,465.5 194.17,444.37 194.17,427.55 ; 194.48,444.16 194.48,427.87 194.17,427.55 ; R29.1@869.74,528.49 891.47,506.76 v1(909.95,506.76) ; U1.18@1074.57,757.89 1102.36,757.89 1106.1,761.63 1126.67,761.63 v1(1134.35,753.95)
  Mid Layer w6.2: v1(186.8,420.19) 194.48,427.87 194.48,443.53 223.02,472.07 503.69,472.07 519.39,456.37 869.75,456.37 1036.56,623.18 1036.56,666.8 1099.61,729.85 1155.28,729.85 1161.39,735.96 1161.39,755.7 1155.45,761.63 1142.03,761.63 v1(1134.35,753.95)
  Bottom Signal Layer w6.2: C96.1@1072.44,822.46 1108.52,786.38 1108.52,779.78 v1(1134.35,753.95)
MCU_PGA1_IN_P: C31.1 R28.1 U1.17 | length 1447.5
  Top Signal Layer w6.2: 206.37,444.37 206.68,444.68 ; R28.1@227.43,332.5 206.37,353.57 206.37,412.2 v1(214.36,420.19) 206.68,427.87 206.68,444.68 ; C31.1@227.5,465.5 206.68,444.68 ; U1.17@1074.57,777.57 1104.06,777.57 1107.8,773.83 1126.67,773.83 v1(1134.35,781.51)
  Mid Layer w6.2: v1(214.36,420.19) 206.68,427.87 206.68,438.48 228.07,459.87 498.64,459.87 514.34,444.17 837.05,444.17 874.8,444.17 1048.76,618.13 1048.76,661.75 1104.66,717.65 1160.33,717.65 1173.59,730.91 1173.59,760.75 1160.51,773.83 1142.03,773.83 v1(1134.35,781.51)
MCU_PGA2_IN_N: C49.1 C97.1 R46.1 R95.1 U1.21 | length 1226.4
  Top Signal Layer w6.2: R95.1@355.89,332.5 386.86,363.47 386.86,424.6 C49.1@345.96,465.5 379.18,498.72 v1(379.18,493.42) ; v1(938.62,734.27) 946.3,741.95 961.05,741.95 1004.17,698.83 U1.21@1074.57,698.83
  Mid Layer w6.2: v1(379.18,493.42) 386.75,500.99 386.75,516.5 419.13,548.88 811.94,548.88 971.18,708.12 971.18,734.83 964.06,741.95 946.3,741.95 v1(938.62,734.27)
  Bottom Signal Layer w6.2: R46.1@358.9,332.5 379.72,353.32 v1(379.72,375.43) ; v1(938.62,734.27) 958.39,734.27 C97.1@977.93,714.72
MCU_PGA2_IN_P: C46.1 R43.1 U1.16 | length 1147.7
  Top Signal Layer w6.2: v1(406.74,493.42) 406.74,498.72 C46.1@439.95,465.5 399.06,424.6 399.06,363.34 R43.1@429.89,332.5 ; v1(938.62,761.83) 946.3,754.15 962.09,754.15 1005.2,797.26 U1.16@1074.57,797.26
  Mid Layer w6.2: v1(406.74,493.42) 398.95,501.21 398.95,511.45 424.18,536.68 816.99,536.68 983.38,703.07 983.38,739.88 969.11,754.15 946.3,754.15 v1(938.62,761.83)
MCU_PGA3_IN_N: C48.1 C98.1 R45.1 R96.1 U1.30 | length 1430.3
  Top Signal Layer w6.2: U1.30@1216.31,557.1 1216.31,528.93 1212.56,525.18 1212.56,510.54 1218.75,504.35 v1(1220.24,504.35)
  Mid Layer w6.2: v1(279.29,394.41) 286.97,386.73 286.97,366.05 316.55,336.46 423.42,336.46 462.25,375.29 504.22,375.29 525.96,353.55 676.79,353.55 717.14,313.2 1055,313.2 1212.56,470.77 1212.56,496.67 v1(1220.24,504.35)
  Bottom Signal Layer w6.2: R96.1@249.97,332.5 273.32,355.85 273.32,363.91 286.97,377.56 286.97,386.73 v1(279.29,394.41) 286.97,402.09 286.97,444.38 C48.1@265.85,465.5 ; R45.1@484.35,332.5 v1@484.35,368.39 ; C98.1@1193.49,456.13 1220.24,482.88 v1(1220.24,504.35)
  other v1: 484.32,368.43
MCU_PGA3_IN_P: C51.1 R48.1 U1.29 | length 1292.8
  Top Signal Layer w6.2: v1(1192.69,504.35) 1194.17,504.35 1200.36,510.54 1200.36,525.2 1196.62,528.94 U1.29@1196.62,557.1
  Mid Layer w6.2: v1(306.85,394.41) 299.17,386.73 299.17,371.1 321.61,348.66 418.37,348.66 457.2,387.49 509.27,387.49 531.01,365.75 681.84,365.75 722.19,325.4 1049.94,325.4 1200.36,475.82 1200.36,496.67 v1(1192.69,504.35)
  Bottom Signal Layer w6.2: R48.1@304.44,332.5 285.52,351.42 285.52,358.86 299.17,372.5 299.17,386.73 v1(306.85,394.41) 299.17,402.09 299.17,444.36 C51.1@320.31,465.5
MCU_TCK: EC1.5 U1.60 U18.14 | length 3797.4
  Top Signal Layer w6: v1(79.02,-76.59) 83.1,-72.51 83.1,-81.81 104.05,-102.76 EC1.5@104.05,-150.67 ; U1.60@1673,797.26 1726.1,797.26 v1(1726.21,797.15)
  Mid Layer w6: v1@82.62,-72.99 v1(79.02,-76.59) 79.02,-103.3 135.86,-160.14 840.51,-160.14 870.75,-129.9 870.75,2.58 928.39,60.22 1229.49,60.22 1355.66,186.39 1355.66,291.65 v1(1375.56,311.55) ; v1(1184.58,1518.82) 1184.58,1499.67 1248.74,1435.51 1248.74,1177.62 1419.11,1007.25 v1(1419.11,930.16) 1419.11,897.86 1489.38,827.59 1695.77,827.59 v1(1726.21,797.15)
  Bottom Signal Layer w6: v1(1184.58,1518.82) 1202.52,1500.88 U18.14@1202.52,1469.06 ; v1(1375.56,311.55) 1396.33,290.78 1499.01,290.78 1542.91,334.68 1542.91,575.71 1498.96,619.67 1498.96,642.05 1419.11,721.9 v1(1419.11,930.16)
MCU_TMS: EC1.3 R13.1 U1.62 U18.16 | length 3979.6
  Top Signal Layer w6: v1(66.77,-41.21) 57.6,-50.38 57.6,-84.42 72.56,-99.38 EC1.3@72.56,-150.67 ; U1.62@1673,836.63 1728.5,836.63 v1(1733.74,841.87)
  Mid Layer w6: v1(66.77,-41.21) 57.49,-50.49 57.49,-111.58 119.01,-173.1 852.58,-173.1 885.62,-140.06 885.62,-0.81 932.06,45.63 1241.71,45.63 1373.5,177.42 v1(1373.5,282.41) ; v1(1253.26,1520.37) 1253.26,1496.23 1263.17,1486.32 1263.17,1186.77 1435.18,1014.76 1435.18,939.67 1443.01,931.84 v1(1443.01,915.08) 1459.77,915.08 1536.26,838.59 1730.46,838.59 v1(1733.74,841.87)
  Bottom Signal Layer w6: U18.16@1253.7,1469.06 v1@1253.7,1519.93 ; v1(1373.5,282.41) 1373.5,249.95 1387.3,236.15 1475.77,236.15 1554.37,314.75 1554.37,579.81 1512.91,621.28 1512.91,645.84 1443.01,715.73 v1(1443.01,915.08) ; R13.1@1649.38,823.47 1669.19,843.28 1732.33,843.28 v1(1733.74,841.87)
MCU_VREFHI: C57.1 S3.1 U1.24 U1.25 | length 218.8
  Top Signal Layer w11.81: S3.1@991.89,536.58 S3.1@999,529.47 ; 1029.91,619.56 1029.91,632.22 1037.47,639.78 U1.24@1074.57,639.78 ; 1030.45,620.09 U1.25@1074.57,620.09
  Top Signal Layer w15: S3.1@991.89,536.58 C57.1@991.89,590.81 1001.16,590.81 1029.91,619.56
MCU_X1: C1.1 S5.1 Y1.1 | length 179.2
  Top Signal Layer w6: S5.1@1784.17,1020.16 1793.97,1020.16 1841.36,1067.55 C1.1@1841.36,1093.03 1841.36,1122.24 1811.84,1151.76 Y1.1@1805.94,1151.76
MCU_X2: R92.1 S5.4 | length 79.1
  Top Signal Layer w8: S5.4@1929.83,1031.98 1929.83,1063.16 R92.1@1963.69,1097.02
MCU_XRSN: C2.1 EC1.120 R18.1 R23.1 S2.4 TP1.1 U1.2 | length 3603.8
  Top Signal Layer w6: U1.2@1074.57,1072.85 1040.43,1072.85 1029.65,1083.63 1029.65,1228.19 1053.28,1251.82 C2.1@1053.28,1292.93 1082.08,1321.73 1370.57,1321.73 1383.12,1309.18 1655.28,1309.18 1726.11,1380.01 v1(2073.02,1380.01) 2073.02,1529.01 2039.19,1562.84 TP1.1@2039.19,1661.81
  Top Signal Layer w11.81: S2.4@1852.89,1797.87 1852.89,1787.49 1873.65,1766.73 1934.59,1766.73 1974,1727.32 R23.1@1974,1661.81 TP1.1@2039.19,1661.81
  Mid Layer w6: v1(2073.02,1380.01) 2096.61,1380.01 2141.48,1335.14 2141.48,506.71 2121.43,486.66 2121.43,54.37 v1(2121.68,54.12)
  Bottom Signal Layer w6: EC1.120@2025.31,-150.67 2017.84,-143.2 2017.84,-50.35 1996.6,-29.11 1996.6,-0.67 2051.39,54.12 v1(2121.68,54.12)
MID_RXD: U17.13 U18.11 | length 462.1
  Top Signal Layer w6: U17.13@951.28,1120.5 v1@992.63,1120.5
  Bottom Signal Layer w6: v1(992.7,1120.57) 971.96,1141.31 971.96,1189.28 1041.17,1258.49 1041.17,1340.28 1125.75,1424.86 U18.11@1125.75,1469.06
MID_TCK_SWDCLK: U17.12 U18.6 | length 530.2
  Top Signal Layer w6: U17.12@951.28,1095.5 v1(1007.42,1095.5)
  Bottom Signal Layer w6: v1(1007.42,1095.5) 1037.75,1125.83 1037.75,1177.75 1088.37,1228.37 1088.37,1309.64 1108.33,1329.6 1203.51,1329.6 1228.11,1305 U18.6@1228.11,1236.77
MID_TDI: U17.15 U18.2 | length 582.3
  Top Signal Layer w6: U17.15@951.28,1170.5 992.63,1170.5 v1(992.7,1170.57)
  Bottom Signal Layer w6: v1(992.7,1170.57) 992.7,1182.14 1056.21,1245.65 1056.21,1326.2 1091.23,1361.22 1237.81,1361.22 1330.47,1268.56 U18.2@1330.47,1236.77
MID_TDO_SWO: U17.10 U18.12 | length 702.8
  Top Signal Layer w6: U17.10@951.28,1045.5 v1(1007.42,1045.5)
  Bottom Signal Layer w6: v1(1007.42,1045.5) 982.09,1045.5 955.59,1072 955.59,1203.2 1023.92,1271.53 1023.92,1354.91 1093.9,1424.89 1093.9,1499.41 1105.46,1510.97 1142.89,1510.97 1151.34,1502.52 U18.12@1151.34,1469.06
MID_TMS_JTAG: U17.14 U18.4 | length 545.9
  Top Signal Layer w6: U17.14@951.28,1145.5 v1(1007.42,1145.5)
  Bottom Signal Layer w6: v1(1007.42,1145.5) 1019.45,1157.53 1019.45,1185.56 1072.37,1238.48 1072.37,1318.52 1097.88,1344.03 1219.78,1344.03 1279.29,1284.52 U18.4@1279.29,1236.77
MID_TXD: U17.11 U18.7 | length 511.4
  Top Signal Layer w6: U17.11@951.28,1070.5 v1@992.63,1070.5
  Bottom Signal Layer w6: v1(992.7,1070.57) 1017.07,1070.57 1055.3,1108.8 1055.3,1179.74 1102.93,1227.37 1102.93,1303.92 1116.96,1317.95 1185.81,1317.95 1202.52,1301.24 U18.7@1202.52,1236.77
NetC5_1: C5.1 U2.3 | length 45.8
  Top Signal Layer w9.84: C5.1@1863.81,1590.54 U2.3@1863.81,1636.31
NetC10_1: C10.1 R24.1 R25.2 R93.1 U4.1
NetC76_1: C76.1 R83.2 U16.96 | length 300.3
  Top Signal Layer w7.87: C76.1@258.79,1377.45 258.79,1381.39 266.67,1389.26 280.78,1389.26 294.67,1403.15 v1(297.51,1403.15) 294.96,1403.15 280.93,1417.19 267.5,1417.19 259.63,1425.06 R83.2@259.63,1429
  Bottom Signal Layer w7.87: U16.96@103.98,1413.3 209.04,1413.3 219.18,1403.15 v1(297.51,1403.15)
NetC85_1: C85.1 C86.1 C87.1 U16.87 U16.115 | length 680.5
  Bottom Signal Layer w7.87: U16.87@103.98,1271.57 380.49,1271.57 446.5,1337.58 U16.115@446.5,1472.36 446.5,1500.5 466.77,1520.77 C85.1@466.77,1544.49 ; C86.1@416.04,1541.52 419.02,1544.49 C85.1@466.77,1544.49 ; C87.1@509.77,1543.73 509,1544.49 C85.1@466.77,1544.49
NetC88_1: C88.1 U16.88 Y2.1 | length 274.8
  Bottom Signal Layer w7.87: Y2.1@-130.5,1266.69 -90.19,1307 -20,1307 16,1271 16,1269.62 33.69,1287.32 U16.88@103.98,1287.32
NetC89_1: C89.1 U16.89 Y2.3 | length 192.3
  Bottom Signal Layer w7.87: Y2.3@-67.5,1353.31 -36.95,1322.76 16,1322.76 35.69,1303.06 U16.89@103.98,1303.06
NetC90_1: C90.1 R89.1 U16.68 | length 326.1
  Bottom Signal Layer w7.87: R89.1@-56.87,1058.21 -56.87,997.5 -59.16,995.21 -45.21,995.21 -36.99,986.99 -36.99,940.9 -37.64,940.25 -37.64,937.74 -19.9,920 26,920 38,932 38,960 50.36,972.36 U16.68@103.98,972.36
NetC95_1: C95.1 R92.2 Y1.3 | length 120.4
  Top Signal Layer w8: Y1.3@1897.25,1212.4 C95.1@1965.94,1212.4 R92.2@1965.94,1160.72
NetD1_1: D1.1 U3.6 | length 96.7
  Top Signal Layer w7.87: D1.1@2147.01,1790.44 2166.6,1770.86 U3.6@2166.6,1701.85
NetD1_2: D1.2 R19.1 | length 101.2
  Top Signal Layer w7.87: D1.2@2147.01,1873.12 2170.86,1896.96 v1(2187.12,1896.96)
  Bottom Signal Layer w7.87: R19.1@2145,1874.91 2167.05,1896.96 v1(2187.12,1896.96)
NetD2_1: D2.1 U3.4 | length 93.4
  Top Signal Layer w7.87: U3.4@2241.4,1701.85 2241.4,1778.84 D2.1@2253.01,1790.45
NetD2_2: D2.2 R20.1 | length 94.5
  Top Signal Layer w7.87: D2.2@2253.01,1873.13 2276.15,1896.26 v1(2291.56,1896.26)
  Bottom Signal Layer w7.87: R20.1@2253.99,1874.91 2275.35,1896.26 v1(2291.56,1896.26)
NetD3_2: D3.2 R25.1 | length 52.3
  Top Signal Layer w11.81: R25.1@1764.3,1508.37 D3.2@1816.61,1508.37
NetD4_1: D4.1 R84.1 | length 67.6
  Bottom Signal Layer w7.87: R84.1@611,1696.45 611,1737.2 D4.1@630,1756.2
NetD5_1: D5.1 R85.1 | length 68.3
  Bottom Signal Layer w7.87: D5.1@552,1757.12 568,1741.12 R85.1@568,1695.47
NetD6_2: D6.2 R71.1 | length 84.2
  Top Signal Layer w19.68: D6.2@1645,1873.14 1694.36,1873.14 R71.1@1719,1848.5
NetD7_2: D7.2 R76.2 | length 73.2
  Top Signal Layer w15.75: R76.2@40,1324.38 102.28,1324.38 D7.2@110,1316.66
NetD9_2: D9.2 T1.1
NetD10_2: D10.2 T1.3
NetEC1_1: EC1.1 R1.2 | length 233.9
  Top Signal Layer w8: R1.2@-10.38,58.44 1.3,46.76 7.16,46.76 41.06,12.86 EC1.1@41.06,-150.67
NetEC1_2: EC1.2 R2.1 | length 235.1
  Bottom Signal Layer w7.99: R2.1@-10.38,58.44 1.38,46.68 9.39,46.68 41.06,15.01 EC1.2@41.06,-150.67
NetR9_1: R9.1 S1.2 | length 113.8
  Top Signal Layer w6: v1@1759.31,583.12 v1(1759.8,583.12) 1782.31,583.12 S1.2@1784.33,581.1
  Bottom Signal Layer w6: v1(1759.8,583.12) R9.1@1759.8,671.11
NetR10_2: R10.2 S1.5 | length 505.5
  Top Signal Layer w6: R10.2@1870.5,809.65 1912.32,851.47 v1(1979.63,851.47) ; S1.5@1949.69,581.1 S1.5@1954.95,581.1 ; S1.5@1954.95,581.1 1962,581.1 1983.76,602.86 v1(1983.76,609.91) S1.5@1954.95,581.1
  Bottom Signal Layer w6: v1(1979.63,851.47) 1925.38,797.22 1925.38,668.29 v1(1983.76,609.91)
NetR16_2: R16.2 R17.1 U1.73 | length 132
  Top Signal Layer w6: U1.73@1673,1053.17 1716.14,1053.17 v1(1724.06,1061.09)
  Bottom Signal Layer w6: v1(1724.06,1061.09) 1740.1,1061.09 R17.1@1749.02,1070.01 1797.63,1070.01 R16.2@1797.92,1069.72
NetR23_2: R23.2 U2.4 | length 78.5
  Top Signal Layer w9.84: U2.4@1911.06,1636.31 1924.49,1636.31 1941.27,1619.53 1953.29,1619.53 R23.2@1974,1598.82
NetR63_1: R63.1 U12.5 | length 76.1
  Top Signal Layer w11.81: v1(235.58,1788) 278.61,1788 U12.5@279.61,1787
  Bottom Signal Layer w11.81: v1(235.58,1788) 265.8,1788 R63.1@266.81,1787
NetR66_1: R66.1 U14.1 | length 138.7
  Top Signal Layer w11.81: v1(1394.02,1611.9) 1412,1629.88 U14.1@1412,1637.76
  Bottom Signal Layer w11.81: R66.1@1317.73,1669 1317.73,1659.83 1365.76,1611.8 v1@1394.02,1611.8
NetR70_1: R70.1 R73.2 U14.3 | length 180
  Top Signal Layer w11.81: U14.3@1463.18,1637.76 1463.24,1637.71 R73.2@1463.24,1574.41
  Bottom Signal Layer w11.81: R70.1@1372.2,1669 1372.2,1668.19 1430.47,1609.92 v1(1463.9,1609.92)
NetR72_2: R72.2 U14.4 | length 80.5
  Top Signal Layer w11.81: U14.4@1488.77,1637.76 1488.77,1616.89 R72.2@1530.95,1574.71
NetR74_2: R74.2 U14.2 | length 83.3
  Top Signal Layer w11.81: R74.2@1392.47,1574.41 1394.56,1574.41 1437.59,1617.44 U14.2@1437.59,1637.76
NetR84_2: R84.2 U16.3 | length 358.1
  Bottom Signal Layer w7.87: R84.2@611,1649.21 611,1617 750,1478 750,1392.99 738.81,1381.8 U16.3@710.28,1381.8
NetR85_2: R85.2 U16.4 | length 364.7
  Bottom Signal Layer w7.87: R85.2@568,1654.13 568,1615.72 670.98,1512.74 670.98,1374.98 ; 671.11,1374.98 680.04,1366.06 U16.4@710.28,1366.06
NetR86_1: R86.1 R87.2 U16.70 | length 155.8
  Bottom Signal Layer w7.87: R86.1@3.13,1058.21 R87.2@3.13,1003.45 3.53,1003.85 U16.70@103.98,1003.85
NetR88_2: R88.2 U16.59 | length 76
  Top Signal Layer w7.87: v1(241.78,828) 261.66,847.89 R88.2@261.66,855.96
  Bottom Signal Layer w7.87: v1@241.78,826.22 v1(241.78,828) U16.59@241.78,866.06
NetR90_1: R90.1 S4.1 U18.1 | length 365.3
  Top Signal Layer w6: R90.1@1171.06,1423.67 1173.78,1423.67 1174.92,1422.53 v1(1174.92,1388.45)
  Top Signal Layer w7.87: R90.1@1174.92,1422.53 1181.59,1415.86 1218.93,1415.86 S4.1@1230.81,1403.98
  Bottom Signal Layer w6: v1(1174.92,1388.45) 1237.43,1388.45 1356.06,1269.82 U18.1@1356.06,1236.77
NetR91_1: R91.1 S4.2 U18.19 | length 240.7
  Top Signal Layer w6: R91.1@1172.37,1355.99 1228.79,1355.99 S4.2@1230.81,1353.98 1273.57,1353.98 1298.07,1378.48 v1(1298.07,1404.33)
  Bottom Signal Layer w6: v1(1298.07,1404.33) 1330.47,1436.73 U18.19@1330.47,1469.06
NetR93_2: R93.2 U4.3 | length 55.8
  Top Signal Layer w11.81: U4.3@1731.87,1599.38 1731.87,1589.44 R93.2@1764.3,1557.02
NetT1_4: T1.4 U12.3
NetT1_6: T1.6 U12.1
POWER_SWITCH_OUT: C68.2 R66.2 R67.2 U14.7 | length 152.7
  Bottom Signal Layer w11.81: R66.2@1317.73,1731.99 1317.73,1768.6 1342.4,1793.27 1415.33,1793.27 1421.2,1799.14
  other v1: 1387.79,1785.69 1387.72,1806.16
VDD_1V2: C6.2 C13.1 C14.1 C15.1 EC1.118 TP5.1 U1.4 U1.71 U1.87 | length 558.6
  Top Signal Layer w11.81: U1.4@1074.57,1033.48 1113.3,1033.48 v1(1122.91,1023.87) ; U1.87@1393.47,1155.53 1393.47,1101.78 1413.88,1081.37 v1(1441.92,1081.37) ; v1@1598.24,1050.16 1598.24,1025.59 1610.03,1013.8 U1.71@1673,1013.8
  PWR w19.68: v1(1994,-71) 1994,-53.09
  Bottom Signal Layer w11.81: C15.1@1087.34,1004.32 1106.89,1023.87 v1(1122.91,1023.87) ; C6.2@1392.92,1147.46 1393.15,1147.23 C6.2@1394.14,1147.23 ; v1@1597.84,1050.16 C14.1@1632.35,1050.16
  Bottom Signal Layer w19.68: C6.2@1404.17,1146.92 1448.21,1146.92 C13.1@1448.94,1147.65 1448.94,1088.39 v1(1441.92,1081.37) ; EC1.118@1993.82,-150.67 1993.82,-71.18 v1(1994,-71)
  other v1: 1597.72,1050.04
VDDA_3V3: C12.1 C24.1 C25.1 C26.2 C27.1 C28.1 L1.2 TP4.1 U1.34 U5.10 U6.10 U7.5 U8.10 U9.10 | length 1032.5
  Top Signal Layer w11.81: v1(120.96,153.05) v1(120.96,153.05) U5.10@121,120.43 ; v1(321.84,137.23) 346.04,137.23 U7.5@351.02,132.24 ; U6.10@462.75,120.43 462.75,153.26 v1(463.62,154.13) ; U9.10@611.07,120.43 611.07,137.22 v1(620.94,147.09) ; U8.10@753.82,120.43 753.82,146.5 v1(768.04,160.72) ; v1(1294.92,649.26) 1294.92,559.62 1296.24,558.3 U1.34@1295.05,557.1
  PWR w11.81: 434.01,174.18 592.72,174.18
  PWR w19.68: v1@122.9,148.66 131.07,156.84 256.16,156.84 288.55,124.45 ; 592.72,174.18 720.03,174.18 740.49,153.73 v1@768.04,153.73
  Bottom Signal Layer w11.81: v1(321.84,137.23) 370.15,137.23 C25.1@375.17,132.21 ; v1(463.62,154.13) 464.06,153.69 C26.2@464.06,113.14 ; C12.1@1261.93,649.14 1262.05,649.26 v1(1294.92,649.26)
  Bottom Signal Layer w19.68: C24.1@120.96,121.38 v1(120.96,153.05) ; C28.1@611.03,114.98 620.94,124.89 v1(620.94,147.09) ; C27.1@753.67,124.74 768.04,139.11 v1(768.04,160.72)
  other v1: 827.86,596.42 786.39,597.18 807.13,597.18
VDDIO_3V3: C19.1 C20.1 C21.1 C23.1 L2.2 TP3.1 U1.3 U1.70 U1.88 | length 928.4
  Top Signal Layer w11.81: U1.3@1074.57,1053.17 v1@1133.43,1053.17 ; U1.88@1373.79,1155.53 v1(1373.79,1199) ; v1(1604.41,986.68) 1611.84,994.11 U1.70@1673,994.11 ; v1@1133.43,1053.17 v1(1133.47,1053.13)
  Bottom Signal Layer w11.81: C21.1@1089.39,1054.36 1090.62,1053.13 v1(1133.47,1053.13) ; v1(1373.79,1199) 1373.79,1200.88 1403.24,1230.33 1404.41,1229.16 C19.1@1413.74,1238.49 ; v1(1604.41,986.68) 1620.79,1003.06 C20.1@1632.35,1003.06
  Bottom Signal Layer w19.68: C20.1@1632.35,1003.06 1632.35,995.57 1696.61,931.31 v1(1725.82,931.31) 1742.91,931.31 1762.87,951.27 C23.1@1768.2,951.27 1830.54,951.27 L2.2@1844.95,965.68 1844.95,960.77 1892.79,912.93 TP3.1@2175.9,912.93
XDS_CC1: J3.A5 R65.2 U13.4 U13.7 | length 282.6
  Top Signal Layer w6.1: J3.A5@124.71,1698.42 254.58,1698.42 282.83,1670.17 U13.7@282.83,1627 U13.4@282.83,1594.13
  Bottom Signal Layer w6.1: R65.2@272,1618 281.9,1627.9 v1(281.9,1650.66)
XDS_CC2: J3.B5 R64.2 U13.5 U13.6 | length 610.8
  Top Signal Layer w6: U13.5@302.51,1594.13 302.51,1634.19 323.39,1655.06 v1(325,1655.06)
  Bottom Signal Layer w6: J3.B5@47.54,1637.39 21.17,1611.02 21.17,1560.83 44.11,1537.89 190.89,1537.89 233,1580 233,1646 256,1669 310.87,1669 324.81,1655.06 v1(325,1655.06) R64.2@325,1615
XDS_D_N: J3.A7 J3.B7 U13.2 U13.9 U16.93 | length 652.2
  Top Signal Layer w6.1: J3.B7@75.1,1684.64 75.1,1682.62 96.56,1661.17 122.59,1661.17 J3.A7@124.71,1659.05 ; v1(164.13,1359.21) 171.13,1366.21 193.13,1366.21 209.58,1382.65 ; v1(203.7,1680.14) 217.97,1680.14 239.66,1658.45 239.66,1644.96 243.46,1641.17 U13.9@243.46,1627 U13.2@243.46,1594.13 243.46,1579.95 239.66,1576.16 239.66,1561.66 209.45,1531.45 209.45,1382.65
  Bottom Signal Layer w6.1: J3.B7@75.1,1684.64 78.72,1684.64 88.42,1674.94 153.81,1674.94 159,1680.14 v1(203.7,1680.14) ; U16.93@103.98,1366.06 134.59,1366.06 136.41,1367.88 155.46,1367.88 v1(164.13,1359.21)
XDS_D_P: J3.A6 J3.B6 U13.1 U13.10 U16.94 | length 613.9
  Top Signal Layer w6.1: J3.A6@124.71,1678.73 164.33,1678.73 v1(182.17,1660.89) 220.11,1660.89 227.56,1653.44 227.56,1644.96 223.77,1641.17 U13.10@223.77,1627 U13.1@223.77,1594.13 223.77,1579.95 227.56,1576.16 227.56,1566.68 197.35,1536.46 197.35,1387.67 ; v1(166,1387) 166,1382.99 165.89,1382.88 170.47,1378.31 188.12,1378.31 197.48,1387.67
  Bottom Signal Layer w6.1: J3.B6@75.1,1653.14 78.72,1653.14 88.42,1662.84 180.22,1662.84 v1(182.17,1660.89) ; U16.94@103.98,1381.8 134.59,1381.8 136.41,1379.98 158.87,1379.98 165.89,1387 v1(166,1387)
XDS_RESET_OUT: U16.40
XDS_RXD: U16.33 U17.6 | length 324.8
  Top Signal Layer w5.98: v1(621,994.32) 621,1022.08 668.95,1070.03 U17.6@756,1070.03
  Bottom Signal Layer w5.98: v1(621,994.32) 621,989.29 619.35,987.64 651.22,955.76 U16.33@651.22,866.06
XDS_TCK_SWDCLK: U16.35 U17.5 | length 349.5
  Top Signal Layer w5.98: v1(579.13,998.21) 579.13,1002.72 596.77,1020.36 597.11,1020.36 606.98,1030.23 606.98,1030.57 671.44,1095.03 U17.5@736.72,1095.03
  Bottom Signal Layer w5.98: v1(579.13,998.21) 579.13,994.71 619.73,954.11 U16.35@619.73,866.06
XDS_TDI: U16.38 U17.2 | length 454.1
  Top Signal Layer w5.98: v1(540.31,1050.68) 539.31,1051.68 578.84,1091.21 612.6,1091.21 691.42,1170.03 U17.2@745,1170.03
  Bottom Signal Layer w5.98: v1(540.31,1050.68) 540.31,990.69 569,962 569,896.57 572.48,893.09 U16.38@572.48,866.06
XDS_TDO_SWO: U16.37 U17.7 | length 314.2
  Top Signal Layer w6: v1(588.57,927.21) 595.81,927.21 641.13,972.53 641.13,1021.5 664.66,1045.03 U17.7@764.02,1045.03
  Bottom Signal Layer w5.98: U16.37@588.23,866.06 588.23,926.87 v1(588.57,927.21)
XDS_TMS_SWDIO: U16.36 U17.3 | length 418.6
  Top Signal Layer w5.98: v1(583.13,1068.21) 608.21,1068.21 685.03,1145.03 U17.3@736.72,1145.03
  Bottom Signal Layer w5.98: v1(583.13,1068.21) 559.13,1044.21 559.13,992.21 607,944.34 607,900 603.98,896.98 U16.36@603.98,866.06
XDS_TXD: U16.34 U17.4 | length 374.7
  Top Signal Layer w5.98: v1(588.5,1038) 594.04,1038 594.84,1037.21 677.66,1120.03 U17.4@736.72,1120.03
  Bottom Signal Layer w5.98: v1(588.5,1038) 589.34,1038 602.13,1025.21 602.13,987.24 635.48,953.89 U16.34@635.48,866.06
